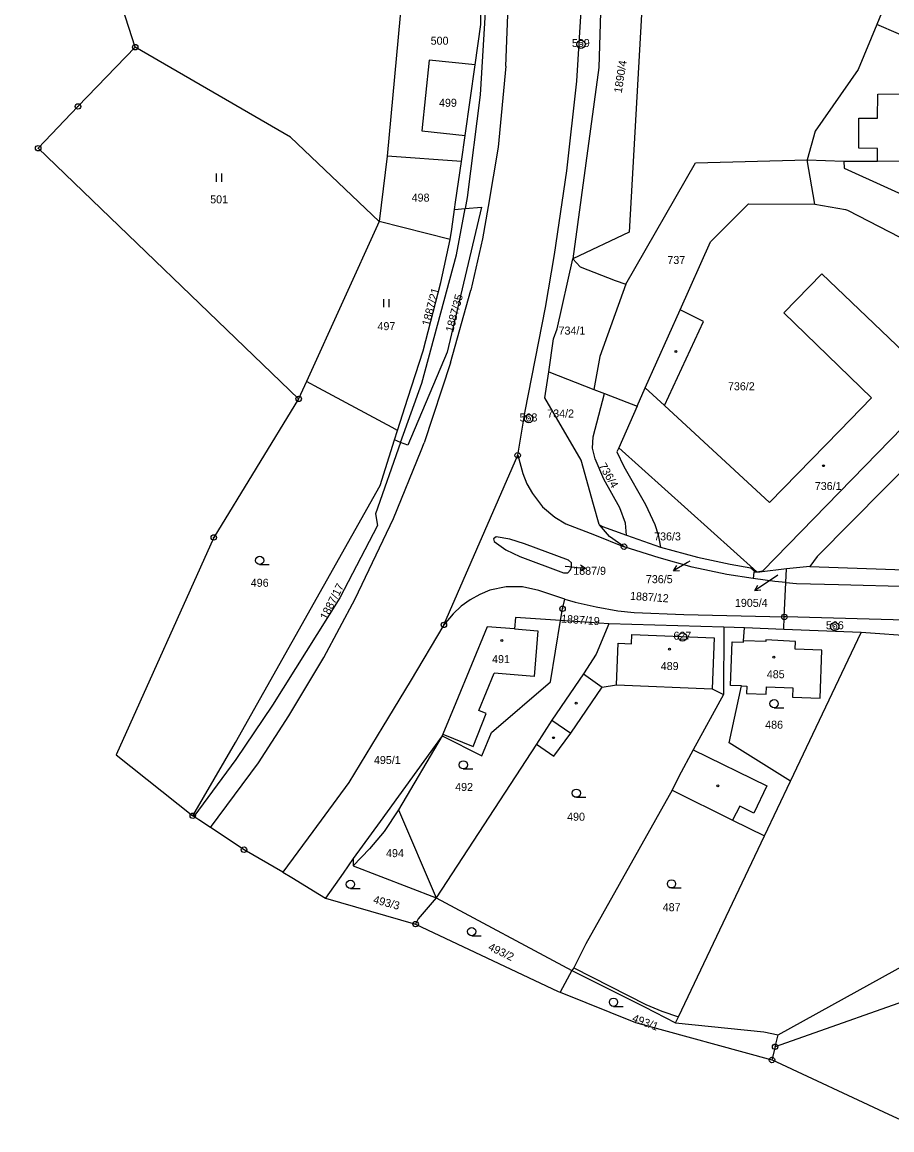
# Model space of a CAD drawing. Extents: x -587171 to -555306, y -1167727 to -1074732.
# Drawn here: x -561125.6 to -560966.9, y -1078447.8 to -1078245.7 of the extents above; entities that cross this region are included whole.
import ezdxf

# ---------------------------------------------------------------- set-up
doc = ezdxf.new("R2010")
doc.units = 0
for name, color, linetype in [('Hranice parcel', 7, 'Continuous'), ('Parcelní čísla', 7, 'Continuous'), ('Pop  PČ popisy', 7, 'Continuous'), ('Vnitřní kresba', 7, 'Continuous'), ('Značky bodu BP', 7, 'Continuous'), ('Značky budov', 7, 'Continuous'), ('Značky kultur', 7, 'Continuous')]:
    doc.layers.add(name, color=color, linetype=linetype)

msp = doc.modelspace()

# ---------------------------------------------------------------- linework, layer by layer
at = {"layer": 'Hranice parcel'}
for p, q in [((-561104.97, -1078250.29), (-561125.62, -1078186.6)), ((-561054.78, -1078224.4), (-561058.99, -1078270.19)), ((-561044.76, -1078266.38), (-561042.93, -1078253.51)), ((-561045.43, -1078271.12), (-561044.76, -1078266.38)), ((-561122.69, -1078268.73), (-561075.15, -1078314.45)), ((-561058.99, -1078270.19), (-561060.43, -1078282.12)), ((-561045.43, -1078271.12), (-561058.99, -1078270.19)), ((-560982.29, -1078270.86), (-560975.6, -1078271.08)), ((-560980.94, -1078278.9), (-560982.29, -1078270.86)), ((-561046.68, -1078279.9), (-561044.76, -1078279.73)), ((-561060.43, -1078282.12), (-561073.72, -1078311.29)), ((-561047.46, -1078285.37), (-561060.43, -1078282.12)), ((-561029.5, -1078309.51), (-561021.25, -1078312.73)), ((-561073.72, -1078311.29), (-561075.15, -1078314.45)), ((-561075.15, -1078314.45), (-561090.64, -1078339.73)), ((-561021.25, -1078312.73), (-561019.33, -1078313.48)), ((-561019.33, -1078313.48), (-561013.37, -1078315.8)), ((-561013.37, -1078315.8), (-561016.72, -1078323.4)), ((-561057.62, -1078321.93), (-561057.08, -1078320.22)), ((-561056.52, -1078322.38), (-561057.62, -1078321.93)), ((-561016.72, -1078323.4), (-560991.5, -1078345.99)), ((-561048.63, -1078355.68), (-561035.16, -1078324.74)), ((-561090.64, -1078339.73), (-561108.44, -1078379.37)), ((-561015.29, -1078339.34), (-561009.09, -1078341.49)), ((-560992.07, -1078346.06), (-560992.2, -1078347.19)), ((-560990.99, -1078346.09), (-560992.07, -1078346.06)), ((-560991.5, -1078345.99), (-560990.99, -1078346.09)), ((-560986.11, -1078345.47), (-560990.99, -1078346.09)), ((-560986.22, -1078347.96), (-560986.11, -1078345.47)), ((-560981.81, -1078345.03), (-560986.11, -1078345.47)), ((-560986.49, -1078354.23), (-560986.22, -1078347.96)), ((-561018.5, -1078355.51), (-561027.32, -1078354.88)), ((-560986.59, -1078356.53), (-560986.49, -1078354.23)), ((-560997.54, -1078356.09), (-561018.5, -1078355.51)), ((-560997.54, -1078356.09), (-560997.61, -1078368.4)), ((-560993.77, -1078356.24), (-560997.54, -1078356.09)), ((-560986.59, -1078356.53), (-560993.77, -1078356.24)), ((-560972.48, -1078357.1), (-560986.59, -1078356.53)), ((-560985.37, -1078384.2), (-560972.48, -1078357.1)), ((-560909.31, -1078361.27), (-560972.48, -1078357.1)), ((-561031.72, -1078377.46), (-561050.01, -1078405.45)), ((-561108.44, -1078379.37), (-561094.47, -1078390.51)), ((-560990.11, -1078394.17), (-560985.37, -1078384.2)), ((-561094.28, -1078390.64), (-561094.47, -1078390.51)), ((-561093.37, -1078391.24), (-561094.28, -1078390.64)), ((-561091.23, -1078392.65), (-561093.37, -1078391.24)), ((-561065.17, -1078398.31), (-561065.17, -1078399.66)), ((-561065.17, -1078399.66), (-561050.01, -1078405.45)), ((-561075.28, -1078402.42), (-561072.42, -1078404.21)), ((-561072.42, -1078404.21), (-561070.25, -1078405.56)), ((-561070.25, -1078405.56), (-561053.79, -1078410.27)), ((-561050.01, -1078405.45), (-561025.28, -1078418.71)), ((-561053.79, -1078410.27), (-561027.74, -1078422.57)), ((-561025.28, -1078418.71), (-561027.38, -1078422.71)), ((-561027.74, -1078422.57), (-561027.38, -1078422.71)), ((-561027.38, -1078422.71), (-561013.66, -1078428.23)), ((-561013.66, -1078428.23), (-560988.74, -1078435.05)), ((-560988.16, -1078432.65), (-560987.61, -1078430.48)), ((-560988.16, -1078432.65), (-560988.74, -1078435.05)), ((-560967.42, -1078444.99), (-560988.74, -1078435.05))]:
    msp.add_line(p, q, dxfattribs=at)
for points in [[(-561053.55, -1078140.65), (-561051.45, -1078152.35), (-561051.98, -1078154.3), (-561050.19, -1078164.24), (-561045.16, -1078185.37), (-561042.13, -1078204.1), (-561041.45, -1078212.84), (-561041.34, -1078214.3), (-561041.1, -1078224.57), (-561040.77, -1078238.78), (-561041.98, -1078259), (-561044.39, -1078277.71), (-561044.76, -1078279.73)], [(-561035.16, -1078324.74), (-561033.82, -1078316.71), (-561030.08, -1078297.81), (-561028.46, -1078288.14), (-561026.16, -1078272.82), (-561024.34, -1078256.49), (-561023.62, -1078244.61), (-561023.93, -1078230.17), (-561024.93, -1078212.43), (-561026.87, -1078193.78)], [(-561042.93, -1078253.51), (-561041.89, -1078246.13), (-561042.06, -1078224.67)], [(-561011.54, -1078226.03), (-561014.79, -1078284.02), (-561025.09, -1078288.93)], [(-561015.53, -1078226.21), (-561015.46, -1078228.09), (-561019.63, -1078229.86), (-561020.33, -1078253.98), (-561025.09, -1078288.93)], [(-560965.38, -1078235.83), (-560967.44, -1078240.9), (-560969.58, -1078246.18)], [(-560969.58, -1078246.18), (-560972.98, -1078254.37), (-560980.87, -1078265.61), (-560982.29, -1078270.86)], [(-560962.01, -1078249.46), (-560965.66, -1078247.88), (-560969.58, -1078246.18)], [(-560975.6, -1078271.08), (-560969.5, -1078271.07), (-560954.05, -1078271.05), (-560953.89, -1078258.74), (-560953.94, -1078254.36), (-560962.01, -1078249.46)], [(-561122.69, -1078268.73), (-561115.43, -1078261.1), (-561104.97, -1078250.29)], [(-561060.43, -1078282.12), (-561076.66, -1078266.68), (-561104.97, -1078250.29)], [(-561042.93, -1078253.51), (-561051.31, -1078252.64), (-561052.64, -1078265.57), (-561044.76, -1078266.38)], [(-561046.68, -1078279.9), (-561046.49, -1078278.54), (-561045.43, -1078271.12)], [(-561015.4, -1078293.51), (-561002.69, -1078271.37), (-560982.29, -1078270.86)], [(-560975.6, -1078271.08), (-560975.58, -1078272.35), (-560960.38, -1078279.23), (-560954.86, -1078282.28)], [(-561044.76, -1078279.73), (-561041.78, -1078279.46), (-561048.03, -1078305.95), (-561055.22, -1078322.91), (-561056.52, -1078322.38)], [(-561056.52, -1078322.38), (-561052.68, -1078311.56), (-561046.3, -1078288.17), (-561044.76, -1078279.73)], [(-561047.46, -1078285.37), (-561047.2, -1078283.52), (-561046.68, -1078279.9)], [(-561005.51, -1078298.23), (-560999.95, -1078285.83), (-560993.04, -1078278.89), (-560980.94, -1078278.9)], [(-560980.94, -1078278.9), (-560975.34, -1078279.89), (-560974.92, -1078280.03), (-560959.72, -1078287.86), (-560959.25, -1078288.13), (-560958.53, -1078288.59), (-560941.65, -1078303.97), (-560943.44, -1078305.78)], [(-561057.08, -1078320.22), (-561055.21, -1078314.31), (-561052.44, -1078305.7), (-561049.16, -1078293.21), (-561047.46, -1078285.37)], [(-561029.5, -1078309.51), (-561028.59, -1078303.48), (-561027.97, -1078301.69), (-561025.09, -1078288.93)], [(-561025.09, -1078288.93), (-561023.74, -1078290.36), (-561017.34, -1078292.86), (-561015.4, -1078293.51)], [(-560991.5, -1078345.99), (-560990.38, -1078345.81), (-560957.85, -1078312.42), (-560979.66, -1078291.65), (-560986.56, -1078298.77), (-560970.59, -1078314.29), (-560976.42, -1078320.26), (-560989.21, -1078333.37), (-561008.36, -1078315.68), (-561001.24, -1078300.34), (-561005.51, -1078298.23)], [(-561015.4, -1078293.51), (-561020.17, -1078306.74), (-561021.25, -1078312.73)], [(-561013.37, -1078315.8), (-561011.88, -1078312.42), (-561005.51, -1078298.23)], [(-560943.44, -1078305.78), (-560980.48, -1078343.18), (-560981.81, -1078345.03)], [(-561020.2, -1078337.45), (-561020.29, -1078337.35), (-561021.34, -1078333.72), (-561023.59, -1078325.64), (-561030.21, -1078314.27), (-561029.5, -1078309.51)], [(-561057.08, -1078320.22), (-561058.09, -1078319.68), (-561071.43, -1078312.52), (-561073.72, -1078311.29)], [(-561015.29, -1078339.34), (-561015.46, -1078337.11), (-561016.54, -1078334.33), (-561019.44, -1078329.08), (-561021.04, -1078325.4), (-561021.47, -1078323.43), (-561021.4, -1078321.4), (-561019.33, -1078313.48)], [(-561094.47, -1078390.51), (-561086.66, -1078377.11), (-561060.27, -1078330.26), (-561057.62, -1078321.93)], [(-561056.52, -1078322.38), (-561061.14, -1078335.4), (-561060.77, -1078337.54), (-561067.64, -1078350.73), (-561079.94, -1078370.32), (-561086.59, -1078380.26), (-561094.28, -1078390.64)], [(-561016.72, -1078323.4), (-561017.05, -1078324.13), (-561015.79, -1078326.78), (-561011.8, -1078333.72), (-561010.13, -1078337.37), (-561009.52, -1078339.28), (-561009.09, -1078341.49)], [(-561035.16, -1078324.74), (-561034.21, -1078328.08), (-561033.48, -1078329.96), (-561032.48, -1078331.72), (-561030.62, -1078334.14), (-561028.35, -1078336.06), (-561026.34, -1078337.22), (-561021.14, -1078339.27), (-561015.74, -1078341.42)], [(-561015.74, -1078341.42), (-561018.38, -1078339.57), (-561020.2, -1078337.45)], [(-561020.2, -1078337.45), (-561019.67, -1078337.76), (-561015.29, -1078339.34)], [(-561025.31, -1078345.15), (-561025.33, -1078344.38), (-561025.89, -1078343.86), (-561033.89, -1078340.88), (-561036.6, -1078340.04), (-561039.1, -1078339.63), (-561039.59, -1078339.96), (-561039.46, -1078340.48), (-561037.33, -1078341.97), (-561034.77, -1078343.22), (-561026.78, -1078346.2), (-561026.02, -1078346.16), (-561025.5, -1078345.62), (-561025.31, -1078345.15)], [(-560992.2, -1078347.19), (-560996.97, -1078346.49), (-561003.28, -1078345.14), (-561009.32, -1078343.46), (-561015.74, -1078341.42)], [(-561009.09, -1078341.49), (-561002.34, -1078343.33), (-560996.37, -1078344.63), (-560992.57, -1078345.29), (-560991.81, -1078345.93), (-560991.5, -1078345.99)], [(-560981.81, -1078345.03), (-560962.87, -1078345.67), (-560957.44, -1078345.55), (-560948.62, -1078343.1), (-560937.51, -1078343.23), (-560916.68, -1078346.89), (-560911.81, -1078347.13), (-560911.8, -1078347.38), (-560905.4, -1078347.6)], [(-561026.55, -1078350.97), (-561031.32, -1078349.4), (-561034.26, -1078348.74), (-561037.28, -1078348.72), (-561040.23, -1078349.33), (-561042.09, -1078350.12), (-561043.82, -1078351.1), (-561045.49, -1078352.24), (-561046.95, -1078353.65), (-561048.63, -1078355.68)], [(-560986.22, -1078347.96), (-560988.19, -1078347.77), (-560992.2, -1078347.19)], [(-560986.22, -1078347.96), (-560984.24, -1078348.15), (-560976.6, -1078348.33), (-560963, -1078348.67)], [(-561027.32, -1078354.88), (-561026.96, -1078352.74), (-561026.55, -1078350.97)], [(-561026.55, -1078350.97), (-561024.64, -1078351.52), (-561020.81, -1078352.37), (-561016.87, -1078353.13), (-561013.9, -1078353.42), (-561004.84, -1078353.8), (-560986.49, -1078354.23)], [(-561027.32, -1078354.88), (-561035.54, -1078354.31), (-561035.71, -1078356.41), (-561040.7, -1078356.01), (-561046.44, -1078369.91), (-561048.82, -1078375.6), (-561048.96, -1078375.94)], [(-561048.96, -1078375.94), (-561041.69, -1078379.57), (-561039.93, -1078375.29), (-561029.18, -1078366.05), (-561027.32, -1078354.88)], [(-561048.63, -1078355.68), (-561054.81, -1078365.98), (-561059.77, -1078374.24), (-561065.99, -1078384.45), (-561072.54, -1078393.35), (-561078.05, -1078400.81)], [(-561018.5, -1078355.51), (-561020.8, -1078361.04), (-561023.16, -1078364.63), (-561028.94, -1078373.05), (-561031.72, -1078377.46)], [(-560985.37, -1078384.2), (-560996.55, -1078377.18), (-560994.31, -1078366.81), (-560993.35, -1078366.85), (-560993.4, -1078368.17), (-560989.81, -1078368.3), (-560989.76, -1078366.98), (-560984.93, -1078367.15), (-560984.98, -1078368.88), (-560979.94, -1078369.05), (-560979.66, -1078360.28), (-560984.48, -1078360.12), (-560984.42, -1078358.69), (-560989.86, -1078358.43), (-560989.87, -1078358.73), (-560993.91, -1078358.58), (-560993.77, -1078356.24)], [(-561031.72, -1078377.46), (-561028.55, -1078379.6), (-561025.43, -1078375.42), (-561019.71, -1078367.03), (-561017.1, -1078366.61), (-560999.63, -1078367.32), (-560997.61, -1078368.4)], [(-560997.61, -1078368.4), (-561003.15, -1078378.48), (-561005.76, -1078383.33), (-561006.96, -1078385.85)], [(-561048.96, -1078375.94), (-561060.26, -1078391.53), (-561065.17, -1078398.31)], [(-561048.96, -1078375.94), (-561056.9, -1078389.45), (-561050.01, -1078405.45)], [(-560910.23, -1078380.03), (-560942.52, -1078412.37), (-560958.5, -1078422.19), (-560988.16, -1078432.65)], [(-560987.61, -1078430.48), (-560958.75, -1078414.54), (-560919.65, -1078388.01), (-560910.23, -1078380.03)], [(-561006.96, -1078385.85), (-561022.71, -1078413.85), (-561024.93, -1078418.22), (-561025.28, -1078418.71)], [(-561006.96, -1078385.85), (-560995.93, -1078391.3), (-560990.11, -1078394.17)], [(-561078.05, -1078400.81), (-561085.11, -1078396.7), (-561091.23, -1078392.65)], [(-561006.34, -1078428.29), (-561005.8, -1078427.16), (-560990.11, -1078394.17)], [(-561065.17, -1078398.31), (-561067.02, -1078400.95), (-561070.25, -1078405.56)], [(-561078.05, -1078400.81), (-561076.38, -1078401.78), (-561075.28, -1078402.42)], [(-561050.01, -1078405.45), (-561053.31, -1078409.3), (-561053.79, -1078410.27)], [(-561025.28, -1078418.71), (-561011.99, -1078425.37), (-561006.34, -1078428.29)], [(-561006.34, -1078428.29), (-560990.25, -1078429.93), (-560987.61, -1078430.48)], [(-560961.41, -1078447.8), (-560964.51, -1078446.35), (-560967.42, -1078444.99)]]:
    msp.add_lwpolyline(points, dxfattribs=at)
at = {"layer": 'Pop  PČ popisy'}
for p, q in [((-561026.51, -1078344.94), (-561025.73, -1078345.04)), ((-561022.75, -1078345.41), (-561023.68, -1078344.79)), ((-561004.13, -1078344.3), (-561006.73, -1078345.8)), ((-561006.73, -1078345.8), (-561006.11, -1078344.87)), ((-561003.74, -1078344.08), (-561004.13, -1078344.3)), ((-561025.73, -1078345.04), (-561022.75, -1078345.41)), ((-561022.75, -1078345.41), (-561023.81, -1078345.78)), ((-561006.73, -1078345.8), (-561005.61, -1078345.73)), ((-560987.67, -1078346.59), (-560989.38, -1078347.74)), ((-560989.38, -1078347.74), (-560991.87, -1078349.42)), ((-560991.87, -1078349.42), (-560991.32, -1078348.44)), ((-560991.87, -1078349.42), (-560990.76, -1078349.27))]:
    msp.add_line(p, q, dxfattribs=at)
at = {"layer": 'Vnitřní kresba'}
for p, q in [((-561037.3, -1078253.77), (-561036.77, -1078239.59)), ((-561037.3, -1078253.77), (-561038.7, -1078268.54)), ((-560969.45, -1078263.27), (-560969.41, -1078258.86)), ((-560969.41, -1078258.86), (-560963.07, -1078258.81)), ((-560972.88, -1078268.73), (-560972.89, -1078263.23)), ((-560972.89, -1078263.23), (-560969.45, -1078263.27)), ((-561038.7, -1078268.54), (-561040.54, -1078279.33)), ((-560969.49, -1078268.77), (-560972.88, -1078268.73)), ((-560969.5, -1078271.07), (-560969.49, -1078268.77)), ((-561040.54, -1078279.33), (-561041.55, -1078285.26)), ((-561041.55, -1078285.26), (-561043.72, -1078294.63)), ((-561047.4, -1078307.86), (-561043.72, -1078294.63)), ((-561047.4, -1078307.86), (-561052.21, -1078322.46)), ((-561011.88, -1078312.42), (-561008.36, -1078315.68)), ((-561052.79, -1078323.89), (-561052.21, -1078322.46)), ((-561057.82, -1078336.3), (-561052.79, -1078323.89)), ((-561064.82, -1078350.94), (-561057.82, -1078336.3)), ((-561070.52, -1078361.63), (-561064.82, -1078350.94)), ((-560986.22, -1078354.24), (-560986.49, -1078354.23)), ((-560929.76, -1078355.69), (-560986.22, -1078354.24)), ((-561035.71, -1078356.41), (-561031.45, -1078356.75)), ((-561031.45, -1078356.75), (-561032.13, -1078365.1)), ((-561017.1, -1078366.61), (-561016.8, -1078359.03)), ((-561016.8, -1078359.03), (-561014.35, -1078359.11)), ((-561014.35, -1078359.11), (-561014.33, -1078357.43)), ((-561014.33, -1078357.43), (-560999.28, -1078358.05)), ((-560999.28, -1078358.05), (-560999.63, -1078367.32)), ((-560996.31, -1078366.74), (-560996.01, -1078358.76)), ((-560996.01, -1078358.76), (-560993.95, -1078358.84)), ((-560993.95, -1078358.84), (-560993.91, -1078358.58)), ((-561076.91, -1078372.27), (-561070.52, -1078361.63)), ((-561042.26, -1078371.29), (-561039.43, -1078364.51)), ((-561032.13, -1078365.1), (-561039.43, -1078364.51)), ((-561023.16, -1078364.63), (-561019.71, -1078367.03)), ((-560994.31, -1078366.81), (-560996.31, -1078366.74)), ((-561082.5, -1078380.83), (-561076.91, -1078372.27)), ((-561043.29, -1078377.86), (-561040.91, -1078371.87)), ((-561040.91, -1078371.87), (-561042.26, -1078371.29)), ((-561028.94, -1078373.05), (-561025.43, -1078375.42)), ((-561048.82, -1078375.6), (-561043.29, -1078377.86)), ((-561003.15, -1078378.48), (-560989.65, -1078385.05)), ((-561091.23, -1078392.65), (-561082.5, -1078380.83)), ((-560989.65, -1078385.05), (-560992.07, -1078390)), ((-560994.61, -1078388.76), (-560995.93, -1078391.3)), ((-560992.07, -1078390), (-560994.61, -1078388.76)), ((-561056.9, -1078389.45), (-561059.52, -1078393.35)), ((-561059.52, -1078393.35), (-561062.19, -1078396.52)), ((-561062.19, -1078396.52), (-561065.17, -1078399.66)), ((-561024.93, -1078418.22), (-561011.76, -1078424.93)), ((-561011.76, -1078424.93), (-561008.86, -1078426.14)), ((-561008.86, -1078426.14), (-561005.8, -1078427.16))]:
    msp.add_line(p, q, dxfattribs=at)
at = {"layer": 'Značky bodu BP'}
for centre, radius in [((-561104.97, -1078250.29), 0.5), ((-561104.97, -1078250.29), 0.5), ((-561023.6, -1078249.76), 0.75), ((-561023.6, -1078249.76), 0.03), ((-561104.97, -1078250.29), 0.0303), ((-561104.97, -1078250.29), 0.0303), ((-561115.43, -1078261.1), 0.5), ((-561115.43, -1078261.1), 0.0303), ((-561122.69, -1078268.73), 0.5), ((-561122.69, -1078268.73), 0.0303), ((-561075.15, -1078314.45), 0.5), ((-561075.15, -1078314.45), 0.0303), ((-561033.14, -1078318.07), 0.75), ((-561033.14, -1078318.07), 0.03), ((-561035.16, -1078324.74), 0.5), ((-561035.16, -1078324.74), 0.0303), ((-561090.64, -1078339.73), 0.5), ((-561090.64, -1078339.73), 0.0303), ((-561015.74, -1078341.42), 0.5), ((-561015.74, -1078341.42), 0.0303), ((-561026.96, -1078352.74), 0.5), ((-561026.96, -1078352.74), 0.0303), ((-560986.49, -1078354.23), 0.5), ((-560986.49, -1078354.23), 0.0303), ((-561048.63, -1078355.68), 0.5), ((-561048.63, -1078355.68), 0.0303), ((-560977.3, -1078355.98), 0.75), ((-560977.3, -1078355.98), 0.03), ((-561005.06, -1078357.88), 0.75), ((-561005.06, -1078357.88), 0.03), ((-561094.47, -1078390.51), 0.5), ((-561094.47, -1078390.51), 0.0303), ((-561085.11, -1078396.7), 0.5), ((-561085.11, -1078396.7), 0.0303), ((-561053.79, -1078410.27), 0.5), ((-561053.79, -1078410.27), 0.0303), ((-560988.16, -1078432.65), 0.5), ((-560988.16, -1078432.65), 0.0303), ((-560988.74, -1078435.05), 0.5), ((-560988.74, -1078435.05), 0.0303)]:
    msp.add_circle(centre, radius, dxfattribs=at)
at = {"layer": 'Značky budov'}
for centre in [(-561006.26, -1078305.83), (-560979.32, -1078326.64), (-561038.06, -1078358.55), (-561007.43, -1078360.1), (-560988.41, -1078361.56), (-561024.46, -1078369.95), (-561028.61, -1078376.26), (-560998.64, -1078385.03)]:
    msp.add_circle(centre, 0.175, dxfattribs=at)
at = {"layer": 'Značky kultur'}
for p, q in [((-561090.15, -1078274.86), (-561090.15, -1078273.36)), ((-561089.15, -1078274.86), (-561089.15, -1078273.36)), ((-561059.6, -1078297.74), (-561059.6, -1078296.24)), ((-561058.6, -1078297.74), (-561058.6, -1078296.24)), ((-561082.26, -1078344.67), (-561080.51, -1078344.67)), ((-560988.35, -1078370.8), (-560986.6, -1078370.8)), ((-561045.09, -1078381.96), (-561043.34, -1078381.96)), ((-561024.44, -1078387.14), (-561022.69, -1078387.14)), ((-561065.69, -1078403.76), (-561063.94, -1078403.76)), ((-561007.08, -1078403.68), (-561005.33, -1078403.68)), ((-561043.55, -1078412.38), (-561041.8, -1078412.38)), ((-561017.66, -1078425.27), (-561015.91, -1078425.27))]:
    msp.add_line(p, q, dxfattribs=at)
for centre in [(-561082.26, -1078343.92), (-560988.35, -1078370.05), (-561045.09, -1078381.21), (-561024.44, -1078386.39), (-561065.69, -1078403.01), (-561007.08, -1078402.93), (-561043.55, -1078411.63), (-561017.66, -1078424.52)]:
    msp.add_circle(centre, 0.75, dxfattribs=at)

# ---------------------------------------------------------------- texts
at = {"layer": 'Parcelní čísla'}
for s, p in [('500', (-561051.04, -1078249.84)), ('499', (-561049.52, -1078261.16)), ('501', (-561091.29, -1078278.78)), ('498', (-561054.51, -1078278.46)), ('737', (-561007.83, -1078289.84)), ('497', (-561060.75, -1078301.91)), ('734/1', (-561027.69, -1078302.72)), ('736/2', (-560996.77, -1078312.88)), ('734/2', (-561029.76, -1078317.85)), ('736/1', (-560980.92, -1078331.08)), ('736/3', (-561010.25, -1078340.27)), ('1887/9', (-561025.01, -1078346.54)), ('736/5', (-561011.75, -1078348.07)), ('496', (-561083.88, -1078348.73)), ('1905/4', (-560995.5, -1078352.39)), ('491', (-561039.83, -1078362.65)), ('489', (-561009.04, -1078363.92)), ('485', (-560989.68, -1078365.41)), ('486', (-560989.98, -1078374.62)), ('495/1', (-561061.4, -1078381.06)), ('492', (-561046.57, -1078385.98)), ('490', (-561026.13, -1078391.41)), ('494', (-561059.19, -1078398.05)), ('487', (-561008.68, -1078407.91))]:
    msp.add_text(s, height=1.46, dxfattribs=at).set_placement(p)
for s, rotation, p in [('1890/4', 81, (-561016.17, -1078258.73)), ('1887/21', 75, (-561051.26, -1078301.25)), ('1887/35', 75, (-561046.95, -1078302.4)), ('736/4', 300, (-561020.39, -1078326.65)), ('1887/17', 63, (-561070.03, -1078354.88)), ('1887/12', 356, (-561014.68, -1078351.09)), ('1887/19', 356, (-561027.28, -1078355.25)), ('493/3', 345, (-561061.64, -1078406.41)), ('493/2', 334, (-561040.68, -1078414.9)), ('493/1', 339, (-561014.38, -1078427.98))]:
    msp.add_text(s, height=1.46, rotation=rotation, dxfattribs=at).set_placement(p)
at = {"layer": 'Značky bodu BP'}
for s, p in [('569', (-561025.26, -1078250.26)), ('568', (-561034.82, -1078318.57)), ('566', (-560978.89, -1078356.48)), ('627', (-561006.72, -1078358.38))]:
    msp.add_text(s, height=1.46, dxfattribs=at).set_placement(p)

doc.saveas('drawing.dxf')
